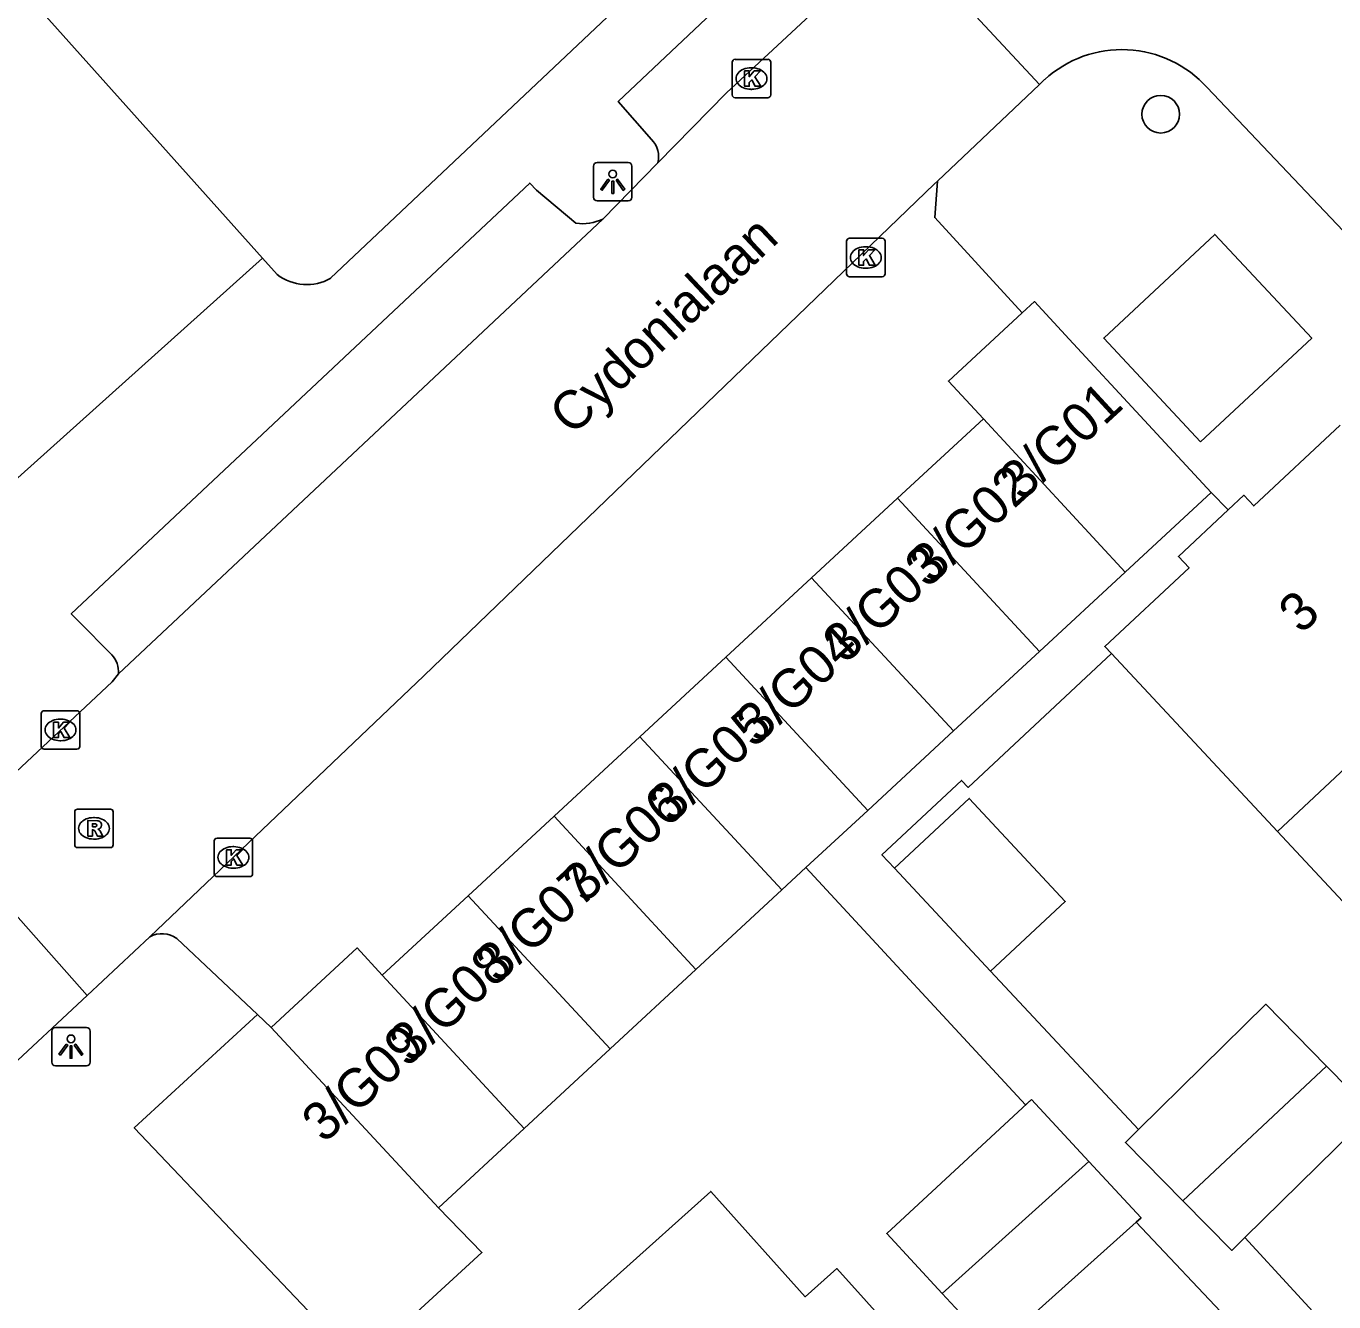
# Model space of a CAD drawing. Extents: x 162347 to 162868, y 381221 to 381813.
# Drawn here: x 162628.37 to 162662.36, y 381502.65 to 381535.82 of the extents above; entities that cross this region are included whole.
import ezdxf

# ---------------------------------------------------------------- set-up
doc = ezdxf.new("R2010")
doc.units = 0
for name, color, linetype in [('IMGEO_Boom', 7, 'Continuous'), ('IMGEO_Kolk', 7, 'Continuous'), ('IMGEO_Lichtpunt', 7, 'Continuous'), ('IMGEO_Openbare_ruimte_label', 7, 'Continuous'), ('IMGEO_Pand', 7, 'Continuous'), ('IMGEO_Pand_nummerreeks', 7, 'Continuous'), ('IMGEO_Parkeervlak_open', 7, 'Continuous'), ('IMGEO_Rijbaan_lokaal_gesloten', 7, 'Continuous'), ('IMGEO_Rijbaan_lokaal_open', 7, 'Continuous'), ('IMGEO_Rioolput', 7, 'Continuous'), ('IMGEO_Voetpad_open', 7, 'Continuous')]:
    doc.layers.add(name, color=color, linetype=linetype)

msp = doc.modelspace()

# ---------------------------------------------------------------- linework, layer by layer
at = {"layer": 'IMGEO_Boom'}
msp.add_circle((162657.861, 381533.53), 0.489, dxfattribs=at)
at = {"layer": 'IMGEO_Kolk'}
for p, q in [((162646.722, 381534.031), (162646.722, 381534.883)), ((162646.797, 381534.957), (162647.649, 381534.957)), ((162647.723, 381534.883), (162647.723, 381534.031)), ((162647.21, 381534.737), (162647.235, 381534.737)), ((162647.233, 381534.177), (162647.208, 381534.177)), ((162647.649, 381533.957), (162646.797, 381533.957)), ((162649.695, 381529.379), (162649.695, 381530.231)), ((162649.77, 381530.305), (162650.622, 381530.305)), ((162650.696, 381530.231), (162650.696, 381529.379)), ((162650.183, 381530.085), (162650.208, 381530.085)), ((162650.206, 381529.525), (162650.181, 381529.525)), ((162650.622, 381529.305), (162649.77, 381529.305)), ((162628.762, 381517.096), (162628.762, 381517.948)), ((162628.837, 381518.022), (162629.689, 381518.022)), ((162629.763, 381517.948), (162629.763, 381517.096)), ((162629.25, 381517.802), (162629.275, 381517.802)), ((162629.273, 381517.242), (162629.248, 381517.242)), ((162629.689, 381517.022), (162628.837, 381517.022)), ((162633.255, 381513.783), (162633.255, 381514.635)), ((162633.33, 381514.709), (162634.182, 381514.709)), ((162633.743, 381514.489), (162633.768, 381514.489)), ((162634.256, 381514.635), (162634.256, 381513.783)), ((162633.766, 381513.929), (162633.741, 381513.929)), ((162634.182, 381513.709), (162633.33, 381513.709))]:
    msp.add_line(p, q, dxfattribs=at)
for points in [[(162646.722, 381534.031), (162646.722, 381534.883)], [(162646.797, 381534.957), (162647.649, 381534.957)], [(162647.723, 381534.883), (162647.723, 381534.031)], [(162647.043, 381534.657), (162647.166, 381534.657), (162647.166, 381534.506), (162647.296, 381534.657), (162647.46, 381534.657), (162647.314, 381534.506), (162647.467, 381534.257), (162647.315, 381534.257), (162647.23, 381534.421), (162647.166, 381534.354), (162647.166, 381534.257), (162647.043, 381534.257), (162647.043, 381534.657)], [(162647.649, 381533.957), (162646.797, 381533.957)], [(162649.695, 381529.379), (162649.695, 381530.231)], [(162649.77, 381530.305), (162650.622, 381530.305)], [(162650.696, 381530.231), (162650.696, 381529.379)], [(162650.016, 381530.005), (162650.139, 381530.005), (162650.139, 381529.854), (162650.269, 381530.005), (162650.433, 381530.005), (162650.287, 381529.854), (162650.44, 381529.605), (162650.288, 381529.605), (162650.203, 381529.769), (162650.139, 381529.702), (162650.139, 381529.605), (162650.016, 381529.605), (162650.016, 381530.005)], [(162650.622, 381529.305), (162649.77, 381529.305)], [(162628.762, 381517.096), (162628.762, 381517.948)], [(162628.837, 381518.022), (162629.689, 381518.022)], [(162629.763, 381517.948), (162629.763, 381517.096)], [(162629.083, 381517.722), (162629.206, 381517.722), (162629.206, 381517.571), (162629.336, 381517.722), (162629.5, 381517.722), (162629.354, 381517.571), (162629.507, 381517.322), (162629.355, 381517.322), (162629.27, 381517.486), (162629.206, 381517.419), (162629.206, 381517.322), (162629.083, 381517.322), (162629.083, 381517.722)], [(162629.689, 381517.022), (162628.837, 381517.022)], [(162633.255, 381513.783), (162633.255, 381514.635)], [(162633.33, 381514.709), (162634.182, 381514.709)], [(162634.256, 381514.635), (162634.256, 381513.783)], [(162633.576, 381514.409), (162633.699, 381514.409), (162633.699, 381514.258), (162633.829, 381514.409), (162633.993, 381514.409), (162633.847, 381514.258), (162634, 381514.009), (162633.848, 381514.009), (162633.763, 381514.173), (162633.699, 381514.106), (162633.699, 381514.009), (162633.576, 381514.009), (162633.576, 381514.409)], [(162634.182, 381513.709), (162633.33, 381513.709)]]:
    msp.add_lwpolyline(points, dxfattribs=at)
for centre, start, end in [((162646.799, 381534.881), 91.552, 178.448), ((162646.799, 381534.881), 91.552, 178.448), ((162647.647, 381534.881), 1.552, 88.448), ((162647.647, 381534.881), 1.552, 88.448), ((162646.799, 381534.033), 181.552, 268.448), ((162646.799, 381534.033), 181.552, 268.448), ((162647.647, 381534.033), 271.552, 358.448), ((162647.647, 381534.033), 271.552, 358.448), ((162649.772, 381530.229), 91.552, 178.448), ((162649.772, 381530.229), 91.552, 178.448), ((162650.62, 381530.229), 1.552, 88.448), ((162650.62, 381530.229), 1.552, 88.448), ((162649.772, 381529.381), 181.552, 268.448), ((162649.772, 381529.381), 181.552, 268.448), ((162650.62, 381529.381), 271.552, 358.448), ((162650.62, 381529.381), 271.552, 358.448), ((162628.839, 381517.946), 91.552, 178.448), ((162628.839, 381517.946), 91.552, 178.448), ((162629.687, 381517.946), 1.552, 88.448), ((162629.687, 381517.946), 1.552, 88.448), ((162628.839, 381517.098), 181.552, 268.448), ((162628.839, 381517.098), 181.552, 268.448), ((162629.687, 381517.098), 271.552, 358.448), ((162629.687, 381517.098), 271.552, 358.448), ((162633.332, 381514.633), 91.552, 178.448), ((162633.332, 381514.633), 91.552, 178.448), ((162634.18, 381514.633), 1.552, 88.448), ((162634.18, 381514.633), 1.552, 88.448), ((162633.332, 381513.785), 181.552, 268.448), ((162633.332, 381513.785), 181.552, 268.448), ((162634.18, 381513.785), 271.552, 358.448), ((162634.18, 381513.785), 271.552, 358.448)]:
    msp.add_arc(centre, 0.0765, start, end, dxfattribs=at)
for centre, major_axis, ratio, start_param, end_param in [((162647.209, 381534.457), (-0.387, 0.002), 0.722429, 4.712389, 7.853982), ((162647.234, 381534.457), (-0.39, 0.002), 0.717154, 1.570796, 4.712389), ((162650.182, 381529.805), (-0.387, 0.002), 0.722429, 4.712389, 7.853982), ((162650.207, 381529.805), (-0.39, 0.002), 0.717154, 1.570796, 4.712389), ((162629.249, 381517.522), (-0.387, 0.002), 0.722429, 4.712389, 7.853982), ((162629.274, 381517.522), (-0.39, 0.002), 0.717154, 1.570796, 4.712389), ((162633.742, 381514.209), (-0.387, 0.002), 0.722429, 4.712389, 7.853982), ((162633.767, 381514.209), (-0.39, 0.002), 0.717154, 1.570796, 4.712389)]:
    msp.add_ellipse(centre, major_axis=major_axis, ratio=ratio, start_param=start_param, end_param=end_param, dxfattribs=at)
at = {"layer": 'IMGEO_Lichtpunt'}
for p, q in [((162643.119, 381532.178), (162643.119, 381531.371)), ((162643.119, 381532.178), (162643.119, 381531.371)), ((162644.021, 381532.273), (162643.213, 381532.273)), ((162644.021, 381532.273), (162643.213, 381532.273)), ((162644.115, 381531.371), (162644.115, 381532.178)), ((162644.115, 381531.371), (162644.115, 381532.178)), ((162643.213, 381531.277), (162644.021, 381531.277)), ((162643.213, 381531.277), (162644.021, 381531.277)), ((162629.937, 381509.788), (162629.129, 381509.788)), ((162629.937, 381509.788), (162629.129, 381509.788)), ((162629.035, 381509.693), (162629.035, 381508.886)), ((162629.035, 381509.693), (162629.035, 381508.886)), ((162630.031, 381508.886), (162630.031, 381509.693)), ((162630.031, 381508.886), (162630.031, 381509.693)), ((162629.129, 381508.792), (162629.937, 381508.792)), ((162629.129, 381508.792), (162629.937, 381508.792))]:
    msp.add_line(p, q, dxfattribs=at)
for points in [[(162643.493, 381531.842), (162643.532, 381531.814), (162643.344, 381531.552), (162643.306, 381531.579), (162643.493, 381531.842)], [(162643.595, 381531.794), (162643.642, 381531.794), (162643.642, 381531.472), (162643.595, 381531.472), (162643.595, 381531.794)], [(162643.705, 381531.814), (162643.743, 381531.841), (162643.93, 381531.579), (162643.891, 381531.551), (162643.705, 381531.814)], [(162629.409, 381509.357), (162629.448, 381509.329), (162629.26, 381509.067), (162629.222, 381509.094), (162629.409, 381509.357)], [(162629.511, 381509.309), (162629.558, 381509.309), (162629.558, 381508.987), (162629.511, 381508.987), (162629.511, 381509.309)], [(162629.621, 381509.329), (162629.659, 381509.356), (162629.846, 381509.094), (162629.807, 381509.066), (162629.621, 381509.329)]]:
    msp.add_lwpolyline(points, dxfattribs=at)
for centre in [(162643.618, 381531.976), (162629.534, 381509.491)]:
    msp.add_circle(centre, 0.0994, dxfattribs=at)
for centre, start, end in [((162643.213, 381532.178), 90, 180), ((162643.213, 381532.178), 90, 180), ((162644.021, 381532.178), 0, 90), ((162644.021, 381532.178), 0, 90), ((162643.213, 381531.371), 180, 270), ((162643.213, 381531.371), 180, 270), ((162644.021, 381531.371), 270, 0), ((162644.021, 381531.371), 270, 360), ((162629.129, 381509.693), 90, 180), ((162629.129, 381509.693), 90, 180), ((162629.937, 381509.693), 0, 90), ((162629.937, 381509.693), 0, 90), ((162629.129, 381508.886), 180, 270), ((162629.129, 381508.886), 180, 270), ((162629.937, 381508.886), 270, 0), ((162629.937, 381508.886), 270, 360)]:
    msp.add_arc(centre, 0.0946, start, end, dxfattribs=at)
at = {"layer": 'IMGEO_Pand'}
for points in [[(162634.513, 381529.784), (162622.804, 381542.861)], [(162627.377, 381523.394), (162634.513, 381529.784)], [(162654.259, 381528.366), (162654.576, 381528.659), (162655.483, 381527.679), (162659.172, 381523.695)], [(162654.259, 381528.366), (162652.344, 381526.592), (162653.251, 381525.612)], [(162651.019, 381523.546), (162653.251, 381525.612)], [(162653.251, 381525.612), (162656.94, 381521.628)], [(162659.611, 381523.241), (162660.022, 381523.625), (162660.281, 381523.348), (162662.529, 381525.448)], [(162656.94, 381521.628), (162659.172, 381523.695)], [(162651.019, 381523.546), (162648.787, 381521.479)], [(162654.708, 381519.562), (162651.019, 381523.546)], [(162656.577, 381519.508), (162656.407, 381519.69), (162658.598, 381521.737), (162658.32, 381522.034), (162659.611, 381523.241)], [(162656.94, 381521.628), (162654.708, 381519.562)], [(162648.787, 381521.479), (162646.555, 381519.412)], [(162652.476, 381517.495), (162648.787, 381521.479)], [(162667.029, 381520.631), (162660.9, 381514.88)], [(162654.708, 381519.562), (162652.476, 381517.495)], [(162644.323, 381517.346), (162646.555, 381519.412)], [(162646.555, 381519.412), (162650.244, 381515.428)], [(162660.9, 381514.88), (162656.577, 381519.508)], [(162644.323, 381517.346), (162642.091, 381515.279)], [(162648.012, 381513.362), (162644.323, 381517.346)], [(162652.476, 381517.495), (162650.244, 381515.428)], [(162650.942, 381513.929), (162652.883, 381515.742), (162655.381, 381513.065), (162653.44, 381511.253)], [(162642.091, 381515.279), (162639.859, 381513.212)], [(162645.78, 381511.295), (162642.091, 381515.279)], [(162650.244, 381515.428), (162648.64, 381513.943)], [(162664.53, 381510.995), (162660.9, 381514.88)], [(162648.64, 381513.943), (162648.012, 381513.362)], [(162650.942, 381513.929), (162653.44, 381511.253)], [(162639.859, 381513.212), (162637.627, 381511.145)], [(162639.859, 381513.212), (162643.548, 381509.228)], [(162648.012, 381513.362), (162645.78, 381511.295)], [(162637.627, 381511.145), (162636.97, 381511.855), (162634.738, 381509.788)], [(162641.316, 381507.162), (162637.627, 381511.145)], [(162645.78, 381511.295), (162643.548, 381509.228)], [(162657.283, 381507.136), (162660.589, 381510.39), (162662.172, 381508.781)], [(162639.084, 381505.095), (162634.738, 381509.788)], [(162643.548, 381509.228), (162641.316, 381507.162)], [(162662.172, 381508.781), (162658.439, 381505.278)], [(162662.172, 381508.781), (162663.354, 381507.58), (162660.048, 381504.326)], [(162654.505, 381507.914), (162650.738, 381504.428), (162652.177, 381502.873)], [(162655.996, 381506.303), (162654.505, 381507.914)], [(162641.316, 381507.162), (162639.084, 381505.095)], [(162658.439, 381505.278), (162656.941, 381506.8), (162657.283, 381507.136)], [(162655.996, 381506.303), (162652.177, 381502.873)], [(162657.223, 381504.726), (162657.35, 381504.84), (162655.996, 381506.303)], [(162644.05, 381494.933), (162639.728, 381499.747), (162640.01, 381500), (162643.73, 381503.34), (162646.164, 381505.525), (162648.622, 381502.787), (162649.439, 381503.52), (162650.983, 381501.801)], [(162660.048, 381504.326), (162659.707, 381503.99), (162658.439, 381505.278)], [(162652.177, 381502.873), (162653.529, 381501.413), (162657.223, 381504.726)]]:
    msp.add_lwpolyline(points, dxfattribs=at)
at = {"layer": 'IMGEO_Parkeervlak_open'}
msp.add_lwpolyline([(162637.034, 381501.017), (162640.217, 381503.934), (162639.084, 381505.095)], dxfattribs=at)
at = {"layer": 'IMGEO_Rijbaan_lokaal_gesloten'}
for points in [[(162644.787, 381532.268), (162646.57, 381534.09), (162651.048, 381538.246)], [(162651.048, 381538.246), (162654.711, 381534.304)], [(162654.711, 381534.304), (162652.056, 381531.792)], [(162643.356, 381530.805), (162644.787, 381532.268)], [(162652.056, 381531.792), (162651.984, 381531.724), (162638.708, 381518.933), (162631.586, 381512.143)], [(162630.767, 381518.982), (162643.356, 381530.805)], [(162626.296, 381514.744), (162630.602, 381518.772), (162630.767, 381518.982)], [(162631.586, 381512.143), (162629.957, 381510.619)]]:
    msp.add_lwpolyline(points, dxfattribs=at)
at = {"layer": 'IMGEO_Rijbaan_lokaal_open'}
for points in [[(162654.711, 381534.304), (162654.844, 381534.43)], [(162659.068, 381534.221), (162664.374, 381528.635)], [(162629.957, 381510.619), (162626.296, 381514.744)], [(162629.957, 381510.619), (162627.765, 381508.572)]]:
    msp.add_lwpolyline(points, dxfattribs=at)
msp.add_arc((162656.853, 381532.241), 2.971, 41.7926, 132.5422, dxfattribs=at)
at = {"layer": 'IMGEO_Rioolput'}
for p, q in [((162629.631, 381514.538), (162629.631, 381515.39)), ((162629.706, 381515.464), (162630.558, 381515.464)), ((162630.119, 381515.244), (162630.144, 381515.244)), ((162630.632, 381515.39), (162630.632, 381514.538)), ((162630.558, 381514.464), (162629.706, 381514.464)), ((162630.142, 381514.684), (162630.117, 381514.684))]:
    msp.add_line(p, q, dxfattribs=at)
for points in [[(162629.631, 381514.538), (162629.631, 381515.39)], [(162629.706, 381515.464), (162630.558, 381515.464)], [(162630.22, 381515.162), (162629.968, 381515.164), (162629.968, 381514.764)], [(162630.632, 381515.39), (162630.632, 381514.538)], [(162629.968, 381514.764), (162630.092, 381514.764), (162630.092, 381514.926), (162630.103, 381514.926)], [(162630.146, 381515.083), (162630.092, 381515.083), (162630.092, 381515.002)], [(162630.092, 381515.002), (162630.144, 381515.002)], [(162630.15, 381514.897), (162630.221, 381514.764), (162630.361, 381514.764), (162630.296, 381514.89)], [(162630.558, 381514.464), (162629.706, 381514.464)]]:
    msp.add_lwpolyline(points, dxfattribs=at)
for centre, radius, start, end in [((162629.708, 381515.388), 0.0765, 91.552, 178.448), ((162629.708, 381515.388), 0.0765, 91.552, 178.448), ((162630.219, 381515.052), 0.109, 350.3612, 89.416), ((162630.556, 381515.388), 0.0765, 1.552, 88.448), ((162630.556, 381515.388), 0.0765, 1.552, 88.448), ((162630.102, 381514.873), 0.0533, 26.0293, 88.6989), ((162630.128, 381515.191), 0.19, 274.7715, 282.9687), ((162630.152, 381514.987), 0.0964, 77.0061, 93.1865), ((162630.166, 381515.044), 0.0378, 276.6634, 79.6772), ((162630.217, 381515.052), 0.112, 277.5842, 350.9817), ((162630.201, 381514.837), 0.108, 29.5134, 73.7905), ((162629.708, 381514.54), 0.0765, 181.552, 268.448), ((162629.708, 381514.54), 0.0765, 181.552, 268.448), ((162630.556, 381514.54), 0.0765, 271.552, 358.448), ((162630.556, 381514.54), 0.0765, 271.552, 358.448)]:
    msp.add_arc(centre, radius, start, end, dxfattribs=at)
for centre, major_axis, ratio, start_param, end_param in [((162630.118, 381514.964), (-0.387, 0.002), 0.722429, 4.712389, 7.853982), ((162630.143, 381514.964), (-0.39, 0.002), 0.717154, 1.570796, 4.712389)]:
    msp.add_ellipse(centre, major_axis=major_axis, ratio=ratio, start_param=start_param, end_param=end_param, dxfattribs=at)
at = {"layer": 'IMGEO_Voetpad_open'}
for points in [[(162653.565, 381545.59), (162636.284, 381529.266)], [(162650.904, 381540.609), (162649.811, 381539.577), (162644.833, 381534.877), (162643.759, 381533.863), (162644.625, 381532.871)], [(162630.592, 381519.475), (162629.722, 381520.357), (162629.54, 381520.541), (162635.362, 381526.012), (162641.461, 381531.742), (162641.638, 381531.554), (162642.66, 381530.698)], [(162652.056, 381531.792), (162651.989, 381530.842), (162654.259, 381528.366)], [(162658.897, 381525.011), (162656.38, 381527.709), (162659.266, 381530.406), (162661.785, 381527.709), (162658.897, 381525.011)], [(162634.895, 381529.36), (162634.513, 381529.784)], [(162659.172, 381523.695), (162659.611, 381523.241)], [(162656.577, 381519.508), (162652.853, 381516.029), (162652.683, 381516.211), (162650.615, 381514.279), (162650.942, 381513.929)], [(162648.64, 381513.943), (162654.349, 381507.775), (162654.505, 381507.914)], [(162634.385, 381510.12), (162632.282, 381512.098)], [(162653.44, 381511.253), (162657.283, 381507.136)], [(162637.034, 381501.017), (162631.179, 381507.177), (162634.385, 381510.12)], [(162634.738, 381509.788), (162634.385, 381510.12)], [(162657.223, 381504.726), (162662.193, 381499.453)], [(162660.048, 381504.326), (162665.145, 381498.782)]]:
    msp.add_lwpolyline(points, dxfattribs=at)
for centre, radius, start, end in [((162644.177, 381532.427), 0.631, 345.3647, 44.7109), ((162642.838, 381531.857), 1.173, 261.2709, 296.2091), ((162635.661, 381530.366), 1.265, 232.7323, 299.5246), ((162630.116, 381519.029), 0.653, 355.911, 43.1756), ((162631.899, 381511.577), 0.647, 53.6725, 118.9289)]:
    msp.add_arc(centre, radius, start, end, dxfattribs=at)

# ---------------------------------------------------------------- texts
at = {"layer": 'IMGEO_Openbare_ruimte_label'}
msp.add_text('Cydonialaan', height=1, rotation=43.2569, dxfattribs=at).set_placement((162642.562, 381525.147))
at = {"layer": 'IMGEO_Pand_nummerreeks'}
for s, rotation, p in [('3/G01', 42.6338, (162654.253, 381523.449)), ('3/G02', 42.6315, (162651.91, 381521.292)), ('3/G03', 42.6315, (162649.658, 381519.219)), ('3', 43.2469, (162661.515, 381519.991)), ('3/G04', 42.6315, (162647.402, 381517.142)), ('3/G05', 42.6338, (162645.145, 381515.065)), ('3/G06', 42.6315, (162642.888, 381512.987)), ('3/G07', 42.6315, (162640.632, 381510.91)), ('3/G08', 42.6338, (162638.377, 381508.835)), ('3/G09', 42.6338, (162636.116, 381506.753))]:
    msp.add_text(s, height=1, rotation=rotation, dxfattribs=at).set_placement(p)

doc.saveas('drawing.dxf')
